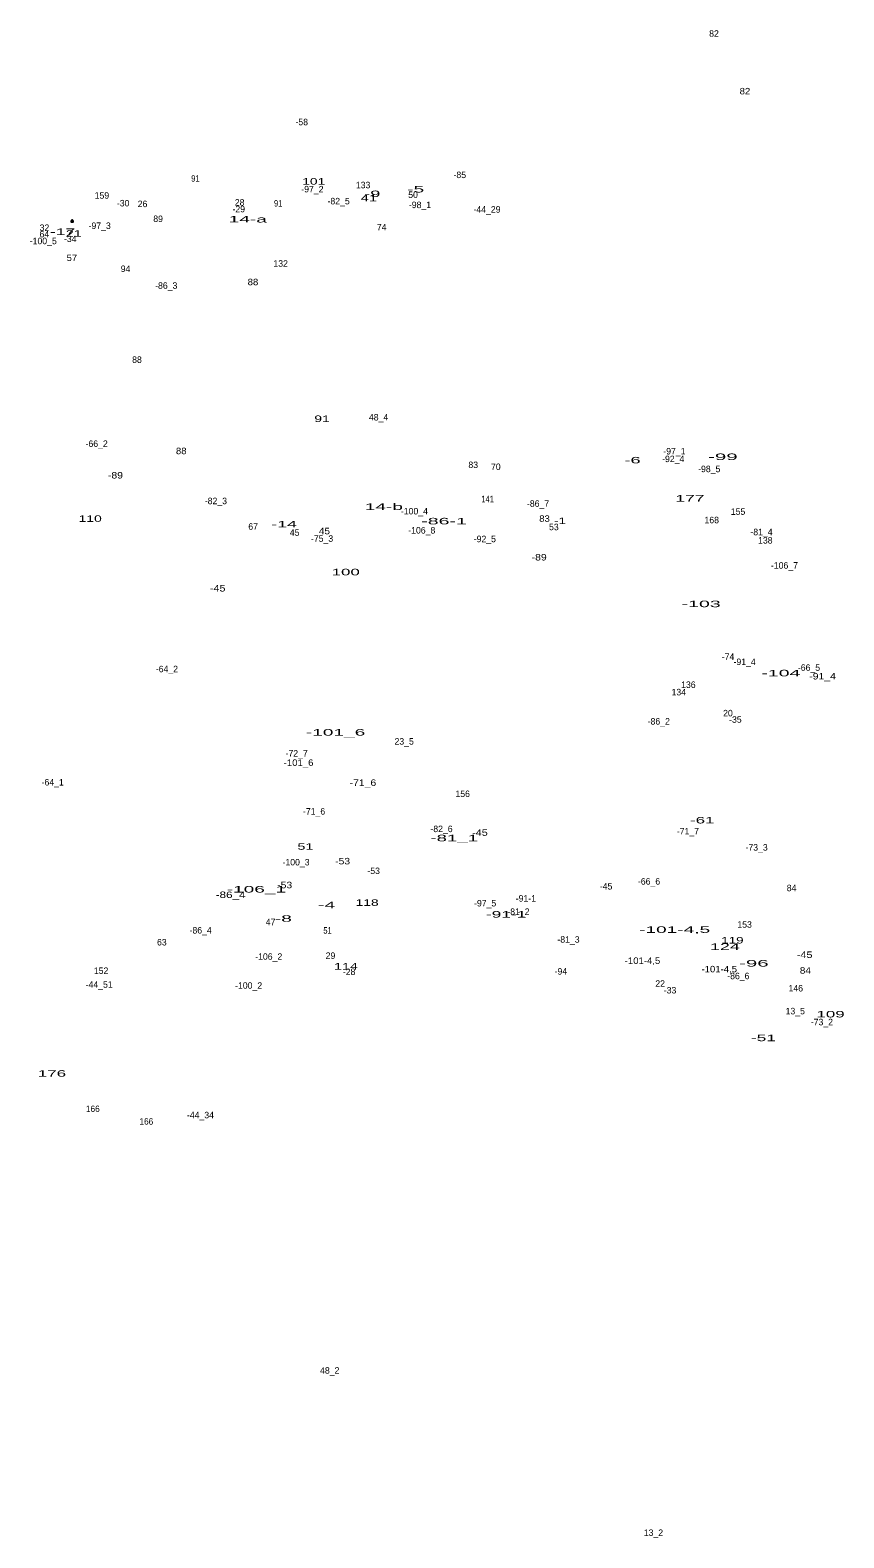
# Model space of a CAD drawing. Extents: x -665231 to -661652, y -987317 to -984562.
# Drawn here: x -663941 to -663439, y -986518 to -985590 of the extents above; entities that cross this region are included whole.
import ezdxf
from ezdxf.enums import TextEntityAlignment as Align

# ---------------------------------------------------------------- set-up
doc = ezdxf.new("R2010")
doc.units = 0
doc.header["$LTSCALE"] = 1.6
doc.layers.add('24', color=7, linetype='Continuous', lineweight=25)

msp = doc.modelspace()

# ---------------------------------------------------------------- linework, layer by layer
at = {"layer": '24'}
for radius in [0.5, 0.0364]:
    msp.add_circle((-663914.83, -985707.35), radius, dxfattribs=at)
msp.add_arc((-663914.833, -985706.976), 0.45, 344.44728, 196.37785, dxfattribs=at)

# ---------------------------------------------------------------- texts
for s, p in [('82', (-663519.219, -985593.564)), ('-58', (-663773.316, -985648.083)), ('-85', (-663675.904, -985680.644)), ('159', (-663896.5, -985693.314)), ('-97_2', (-663766.752, -985689.445)), ('133', (-663735.495, -985686.917)), ('50', (-663704.708, -985692.887)), ('-30', (-663883.402, -985698.087)), ('26', (-663871.458, -985698.543)), ('-29', (-663812.142, -985701.714)), ('28', (-663811.594, -985697.599)), ('-82_5', (-663750.581, -985696.827)), ('-98_1', (-663700.439, -985699.13)), ('-44_29', (-663659.128, -985701.919)), ('-97_3', (-663897.865, -985711.98)), ('89', (-663861.843, -985707.706)), ('74', (-663724.056, -985712.908)), ('-100_5', (-663932.636, -985721.366)), ('32', (-663931.912, -985713.226)), ('64', (-663931.963, -985717.164)), ('-34', (-663915.985, -985720.056)), ('94', (-663881.913, -985738.488)), ('132', (-663786.321, -985735.228)), ('-86_3', (-663856.839, -985748.837)), ('88', (-663874.881, -985794.478)), ('48_4', (-663725.956, -985829.967)), ('-66_2', (-663899.728, -985846.259)), ('-97_1', (-663543.616, -985850.907)), ('83', (-663667.616, -985859.274)), ('70', (-663653.701, -985860.465)), ('-92_4', (-663544.357, -985855.612)), ('-98_5', (-663522.149, -985861.805)), ('-82_3', (-663826.232, -985881.524)), ('-100_4', (-663703.861, -985887.826)), ('-86_7', (-663627.672, -985883.132)), ('155', (-663504.388, -985888.087)), ('67', (-663803.291, -985897.264)), ('53', (-663617.913, -985897.545)), ('168', (-663520.611, -985893.266)), ('45', (-663777.713, -985900.988)), ('-75_3', (-663760.799, -985904.681)), ('-106_8', (-663699.332, -985899.607)), ('-92_5', (-663660.465, -985904.947)), ('-81_4', (-663489.937, -985900.652)), ('138', (-663487.586, -985905.774)), ('-106_7', (-663475.796, -985921.225)), ('-74', (-663510.576, -985977.466)), ('-91_4', (-663500.333, -985980.609)), ('-64_2', (-663856.419, -985985.069)), ('-66_5', (-663460.679, -985984.178)), ('134', (-663540.919, -985999.28)), ('136', (-663535.01, -985994.71)), ('-86_2', (-663553.258, -986017.293)), ('20', (-663510.616, -986012.229)), ('-35', (-663506.04, -986016.171)), ('-72_7', (-663776.447, -986036.994)), ('23_5', (-663710.182, -986029.636)), ('-64_1', (-663926.825, -986054.816)), ('156', (-663674.125, -986061.916)), ('-71_6', (-663765.712, -986072.756)), ('-82_6', (-663687.165, -986083.531)), ('-71_7', (-663535.301, -986084.994)), ('-73_3', (-663492.959, -986094.929)), ('-100_3', (-663776.823, -986104.056)), ('-53', (-663728.983, -986109.38)), ('-45', (-663585.753, -986118.889)), ('-66_6', (-663559.262, -986115.876)), ('84', (-663471.387, -986119.94)), ('-97_5', (-663660.274, -986129.317)), ('-91-1', (-663635.174, -986126.369)), ('-81_2', (-663639.758, -986134.557)), ('-86_4', (-663835.63, -986146.003)), ('47', (-663792.543, -986140.888)), ('153', (-663500.361, -986142.429)), ('63', (-663859.543, -986153.357)), ('-81_3', (-663608.895, -986151.642)), ('-106_2', (-663793.657, -986162.205)), ('29', (-663755.593, -986161.648)), ('152', (-663896.995, -986170.922)), ('-28', (-663744.114, -986171.586)), ('-94', (-663613.607, -986171.309)), ('-86_6', (-663504.222, -986174.144)), ('-44_51', (-663898.177, -986179.404)), ('-100_2', (-663806.062, -986180.022)), ('22', (-663552.419, -986178.8)), ('-33', (-663546.321, -986182.923)), ('146', (-663468.82, -986181.708)), ('13_5', (-663469.145, -986195.787)), ('-73_2', (-663452.721, -986202.535)), ('-44_34', (-663835.755, -986259.833)), ('48_2', (-663756.055, -986417.151)), ('13_2', (-663556.551, -986517.124))]:
    msp.add_text(s, height=4, dxfattribs=at).set_placement(p, align=Align.CENTER)
for s, width, p in [('82', 1.1, (-663500.144, -985629.082)), ('91', 0.8, (-663838.87, -985682.876)), ('101', 1.6, (-663765.938, -985684.665)), ('-9', 2.1, (-663729.844, -985692.324)), ('-5', 2.2, (-663703.062, -985689.505)), ('91', 0.8, (-663787.834, -985698.169)), ('41', 1.7, (-663731.965, -985694.903)), ('14-a', 2.2, (-663806.573, -985707.988)), ('-17', 2, (-663920.732, -985715.689)), ('21', 1.65, (-663913.849, -985716.721)), ('57', 1.1, (-663915.001, -985731.723)), ('88', 1.1, (-663803.373, -985746.628)), ('91', 1.6, (-663760.802, -985830.867)), ('88', 1.1, (-663847.588, -985850.715)), ('-6', 2.1, (-663569.447, -985856.399)), ('-99', 2.35, (-663513.747, -985854.323)), ('-89', 1.2, (-663888.138, -985865.698)), ('177', 2, (-663534.056, -985879.908)), ('14-b', 2.2, (-663722.71, -985885.059)), ('141', 0.8, (-663658.758, -985880.343)), ('110', 1.6, (-663903.708, -985892.394)), ('-14', 2.05, (-663784.181, -985895.852)), ('-86-1', 2.25, (-663685.594, -985893.954)), ('83', 1.1, (-663623.667, -985892.38)), ('-1', 1.55, (-663614.126, -985893.774)), ('45', 1.15, (-663759.336, -985900.067)), ('-89', 1.2, (-663626.97, -985916.194)), ('100', 1.95, (-663746.227, -985925.332)), ('-45', 1.25, (-663825.139, -985935.313)), ('-103', 2.25, (-663527.145, -985944.957)), ('-104', 2.25, (-663477.998, -985987.564)), ('-91_4', 1.2, (-663452.307, -985989.509)), ('-101_6', 2.2, (-663752.476, -986024.071)), ('-101_6', 1.1, (-663775.28, -986042.757)), ('-71_6', 1.2, (-663735.603, -986055.057)), ('-61', 1.95, (-663526.465, -986078.193)), ('-81_1', 2.15, (-663679.321, -986089.183)), ('-45', 1.25, (-663663.501, -986085.82)), ('51', 1.65, (-663771.053, -986094.406)), ('-53', 1.2, (-663748.134, -986103.41)), ('-106_1', 2.2, (-663801.27, -986120.745)), ('-53', 1.2, (-663783.833, -986118.115)), ('-86_4', 1.35, (-663817.148, -986124.135)), ('-4', 2.25, (-663757.994, -986130.455)), ('118', 1.6, (-663733.042, -986128.947)), ('-8', 2.2, (-663784.655, -986138.749)), ('-91-1', 2, (-663647.331, -986136.19)), ('51', 0.8, (-663757.421, -986146.082)), ('-101-4,5', 2.2, (-663543.481, -986145.597)), ('124', 2.05, (-663512.479, -986156.074)), ('119', 1.55, (-663507.898, -986152.161)), ('-101-4,5', 1.1, (-663563.294, -986164.725)), ('-96', 2.35, (-663494.645, -986166.362)), ('-45', 1.25, (-663463.354, -986161.056)), ('114', 1.65, (-663746.073, -986168.201)), ('-101-4,5', 1.1, (-663515.99, -986169.921)), ('84', 1.15, (-663462.902, -986170.75)), ('109', 1.95, (-663447.385, -986197.696)), ('-51', 2, (-663488.73, -986212.314)), ('176', 1.95, (-663927.256, -986234.199)), ('166', 0.95, (-663902.092, -986255.984)), ('166', 0.95, (-663869.089, -986263.753))]:
    msp.add_text(s, height=4, dxfattribs=dict(at, width=width)).set_placement(p, align=Align.CENTER)

doc.saveas('drawing.dxf')
